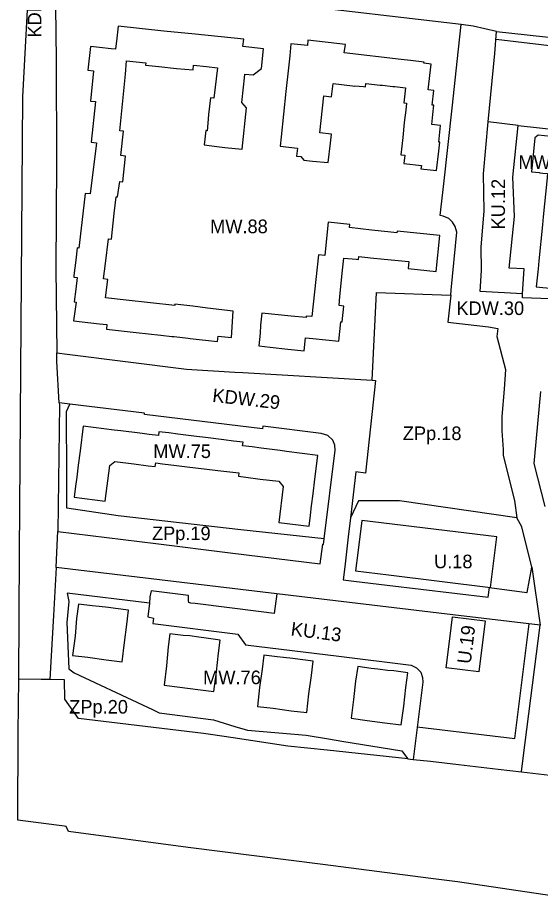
# Model space of a CAD drawing. Extents: x 7424434 to 7425898, y 5541432 to 5542659.
# Drawn here: x 7424612.8 to 7424804.8, y 5541529.8 to 5541854.6 of the extents above; entities that cross this region are included whole.
import ezdxf

# ---------------------------------------------------------------- set-up
doc = ezdxf.new("R2010")
doc.units = 0
for name, color, linetype in [('linie rozgraniczające', 7, 'Continuous'), ('nieprzekraczalne linie zabudowy', 7, 'Continuous'), ('obowiazujace linie zabudowy', 7, 'Continuous'), ('przeznaczenia terenów', 7, 'Continuous')]:
    doc.layers.add(name, color=color, linetype=linetype)

msp = doc.modelspace()

# ---------------------------------------------------------------- linework, layer by layer
at = {"layer": 'linie rozgraniczające'}
for p, q in [((7424614.73, 5541825.47), (7424617.47, 5541879.28)), ((7424626.71, 5541858.72), (7424626.92, 5541838.97)), ((7424775.7, 5541852), (7424710.49, 5541859.62)), ((7424774.72, 5541843.02), (7424775.7, 5541852)), ((7424780.17, 5541851.48), (7424775.7, 5541852)), ((7424788.7, 5541849.47), (7424780.17, 5541851.48)), ((7424788.02, 5541841.39), (7424788.7, 5541849.47)), ((7424788.7, 5541849.47), (7424827.16, 5541845.27)), ((7424772.35, 5541821.35), (7424774.72, 5541843.02)), ((7424785.67, 5541816.27), (7424788.02, 5541841.39)), ((7424626.92, 5541838.97), (7424627, 5541801.52)), ((7424613.5, 5541657.81), (7424614.73, 5541825.47)), ((7424769.3, 5541793.46), (7424772.35, 5541821.35)), ((7424783.89, 5541797.23), (7424785.67, 5541816.27)), ((7424796.69, 5541814.95), (7424785.67, 5541816.27)), ((7424794.7, 5541795.91), (7424796.69, 5541814.95)), ((7424796.69, 5541814.95), (7424823.5, 5541811.99)), ((7424627, 5541801.52), (7424626.85, 5541762.39)), ((7424784.16, 5541783.5), (7424783.89, 5541797.23)), ((7424795.25, 5541781.53), (7424794.7, 5541795.91)), ((7424768.03, 5541781.81), (7424769.3, 5541793.46)), ((7424783, 5541770.36), (7424784.16, 5541783.5)), ((7424769.11, 5541781.68), (7424768.03, 5541781.81)), ((7424771.15, 5541780.72), (7424769.11, 5541781.68)), ((7424772.47, 5541779.45), (7424771.15, 5541780.72)), ((7424773.53, 5541777.86), (7424772.47, 5541779.45)), ((7424793.29, 5541762.54), (7424795.25, 5541781.53)), ((7424774.13, 5541775.69), (7424773.53, 5541777.86)), ((7424772.08, 5541754.48), (7424774.13, 5541775.69)), ((7424783.12, 5541761.62), (7424783, 5541770.36)), ((7424626.85, 5541762.39), (7424627.15, 5541731.4)), ((7424782.68, 5541753.97), (7424783.12, 5541761.62)), ((7424798.83, 5541762.22), (7424793.29, 5541762.54)), ((7424798.3, 5541753.07), (7424798.83, 5541762.22)), ((7424742.99, 5541721.35), (7424744.63, 5541753.59)), ((7424744.63, 5541753.59), (7424771.9, 5541752.56)), ((7424771.9, 5541752.56), (7424772.08, 5541754.48)), ((7424798.3, 5541753.07), (7424782.68, 5541753.97)), ((7424771.9, 5541752.56), (7424770.83, 5541742.67)), ((7424798.21, 5541751.57), (7424798.3, 5541753.07)), ((7424808.23, 5541751.19), (7424798.21, 5541751.57)), ((7424770.83, 5541742.67), (7424785.72, 5541740.94)), ((7424785.72, 5541740.94), (7424789.13, 5541740.32)), ((7424789.13, 5541740.32), (7424788.86, 5541737.35)), ((7424788.86, 5541737.35), (7424792.02, 5541725.28)), ((7424627.15, 5541731.4), (7424631.02, 5541730.92)), ((7424627.18, 5541728.22), (7424627.15, 5541731.4)), ((7424631.02, 5541730.92), (7424674.77, 5541725.4)), ((7424628.06, 5541713.02), (7424627.18, 5541728.22)), ((7424674.77, 5541725.4), (7424692.52, 5541724.35)), ((7424692.52, 5541724.35), (7424695.52, 5541724.17)), ((7424695.52, 5541724.17), (7424740.9, 5541721.48)), ((7424792.02, 5541725.28), (7424791.47, 5541718.1)), ((7424744.22, 5541721.27), (7424740.61, 5541687.19)), ((7424740.9, 5541721.48), (7424740.93, 5541721.48)), ((7424740.93, 5541721.48), (7424742.99, 5541721.35)), ((7424742.99, 5541721.35), (7424744.22, 5541721.27)), ((7424791.47, 5541718.1), (7424790.65, 5541707.98)), ((7424804.86, 5541717.21), (7424802.63, 5541693.48)), ((7424628.1, 5541712.33), (7424627.5, 5541665.79)), ((7424631.9, 5541712.56), (7424628.06, 5541713.02)), ((7424628.06, 5541713.02), (7424628.1, 5541712.33)), ((7424630.69, 5541709.84), (7424631.9, 5541712.56)), ((7424659.37, 5541709.26), (7424631.9, 5541712.56)), ((7424630.82, 5541685.82), (7424630.69, 5541709.84)), ((7424659.32, 5541708.73), (7424659.37, 5541709.26)), ((7424702.71, 5541703.45), (7424659.32, 5541708.73)), ((7424790.65, 5541707.98), (7424790.62, 5541702.7)), ((7424702.84, 5541704.45), (7424702.71, 5541703.45)), ((7424724.33, 5541701.78), (7424702.84, 5541704.45)), ((7424726.78, 5541701.06), (7424724.33, 5541701.78)), ((7424790.62, 5541702.7), (7424791.08, 5541695.94)), ((7424728.52, 5541699.35), (7424726.78, 5541701.06)), ((7424729.35, 5541697.52), (7424728.52, 5541699.35)), ((7424725.33, 5541663), (7424729.36, 5541695.67)), ((7424729.36, 5541695.67), (7424729.35, 5541697.52)), ((7424791.08, 5541695.94), (7424791.18, 5541693.7)), ((7424791.18, 5541693.7), (7424795.32, 5541677.09)), ((7424802.63, 5541693.48), (7424802.41, 5541690.77)), ((7424802.41, 5541690.77), (7424806.44, 5541674.91)), ((7424630.89, 5541674.29), (7424630.82, 5541685.82)), ((7424736.97, 5541687.64), (7424735.02, 5541670.8)), ((7424740.61, 5541687.19), (7424736.97, 5541687.64)), ((7424737.97, 5541677.06), (7424735.02, 5541670.8)), ((7424753.11, 5541676.98), (7424737.97, 5541677.06)), ((7424796.14, 5541670.72), (7424753.11, 5541676.98)), ((7424795.32, 5541677.09), (7424796.14, 5541670.72)), ((7424649.75, 5541671.49), (7424630.89, 5541674.29)), ((7424694.71, 5541666.4), (7424649.75, 5541671.49)), ((7424735.02, 5541670.8), (7424734.21, 5541663.81)), ((7424798, 5541667.52), (7424796.14, 5541670.72)), ((7424627.47, 5541663.47), (7424627.5, 5541665.79)), ((7424627.5, 5541665.79), (7424663.55, 5541661.36)), ((7424725.33, 5541663), (7424694.71, 5541666.4)), ((7424801.7, 5541652.63), (7424798, 5541667.52)), ((7424626.87, 5541652.56), (7424627.47, 5541663.47)), ((7424725.09, 5541661.01), (7424725.33, 5541663)), ((7424734.21, 5541663.81), (7424732.93, 5541652.76)), ((7424663.55, 5541661.36), (7424690.81, 5541657.92)), ((7424723.94, 5541653.86), (7424724.84, 5541661.07)), ((7424724.84, 5541661.07), (7424725.09, 5541661.01)), ((7424613.16, 5541611.54), (7424613.5, 5541657.81)), ((7424690.81, 5541657.92), (7424723.94, 5541653.86)), ((7424732.93, 5541652.76), (7424732.38, 5541647.99)), ((7424626.87, 5541652.56), (7424626.38, 5541643.65)), ((7424708.02, 5541642.85), (7424626.87, 5541652.56)), ((7424799.99, 5541643.37), (7424801.7, 5541652.63)), ((7424801.7, 5541652.63), (7424804.72, 5541631.32)), ((7424732.38, 5541647.99), (7424736.33, 5541647.52)), ((7424736.33, 5541647.52), (7424748.53, 5541646.06)), ((7424626.38, 5541643.65), (7424625.89, 5541634.9)), ((7424661.18, 5541639.46), (7424631.01, 5541643.09)), ((7424631.01, 5541643.09), (7424631.59, 5541640.06)), ((7424661.85, 5541643.92), (7424661.28, 5541641.7)), ((7424663.83, 5541643.68), (7424661.85, 5541643.92)), ((7424675.53, 5541642.27), (7424663.83, 5541643.68)), ((7424748.53, 5541646.06), (7424785.68, 5541641.62)), ((7424785.68, 5541641.62), (7424786.11, 5541645.23)), ((7424786.11, 5541645.23), (7424799.81, 5541643.39)), ((7424799.81, 5541643.39), (7424799.99, 5541643.37)), ((7424631.59, 5541640.06), (7424630.86, 5541632.33)), ((7424661.28, 5541641.7), (7424661.18, 5541639.46)), ((7424675.52, 5541640.21), (7424675.53, 5541642.27)), ((7424675.67, 5541639.71), (7424675.52, 5541640.21)), ((7424676.45, 5541639.47), (7424675.67, 5541639.71)), ((7424708.02, 5541642.85), (7424706.99, 5541635.67)), ((7424772.65, 5541635.12), (7424708.02, 5541642.85)), ((7424661.18, 5541639.46), (7424660.55, 5541634.38)), ((7424677.96, 5541639.28), (7424676.45, 5541639.47)), ((7424702.23, 5541636.26), (7424677.96, 5541639.28)), ((7424625.89, 5541634.9), (7424625.07, 5541620.11)), ((7424660.55, 5541634.38), (7424662.73, 5541633.96)), ((7424662.73, 5541633.96), (7424662.46, 5541631.89)), ((7424706.99, 5541635.67), (7424702.23, 5541636.26)), ((7424771.52, 5541626.36), (7424772.55, 5541634.33)), ((7424772.55, 5541634.33), (7424784.56, 5541632.91)), ((7424804.72, 5541631.32), (7424772.65, 5541635.12)), ((7424630.86, 5541632.33), (7424631.58, 5541615.32)), ((7424662.46, 5541631.89), (7424693.7, 5541628.02)), ((7424784.56, 5541632.91), (7424782.16, 5541614.22)), ((7424798.54, 5541582.44), (7424804.72, 5541631.32)), ((7424693.7, 5541628.02), (7424696.44, 5541624.06)), ((7424696.44, 5541624.06), (7424730.76, 5541619.89)), ((7424770.15, 5541615.7), (7424771.52, 5541626.36)), ((7424625.07, 5541620.11), (7424624.59, 5541611.38)), ((7424730.76, 5541619.89), (7424757.33, 5541616.62)), ((7424631.58, 5541615.32), (7424633.57, 5541613.85)), ((7424633.57, 5541613.85), (7424658.59, 5541602.06)), ((7424757.33, 5541616.62), (7424759.36, 5541615.62)), ((7424759.36, 5541615.62), (7424760.91, 5541614.01)), ((7424760.91, 5541614.01), (7424761.55, 5541612.07)), ((7424782.16, 5541614.22), (7424770.15, 5541615.7)), ((7424613.02, 5541591.89), (7424613.16, 5541611.54)), ((7424621.47, 5541611.42), (7424613.16, 5541611.54)), ((7424624.59, 5541611.38), (7424621.47, 5541611.42)), ((7424630.02, 5541611.3), (7424624.59, 5541611.38)), ((7424630.12, 5541604.1), (7424630.02, 5541611.3)), ((7424761.55, 5541612.07), (7424761.62, 5541610.35)), ((7424761.62, 5541610.35), (7424758.13, 5541582)), ((7424635.1, 5541597.09), (7424630.12, 5541604.1)), ((7424658.59, 5541602.06), (7424662.37, 5541600.28)), ((7424662.37, 5541600.28), (7424664.02, 5541599.5)), ((7424664.02, 5541599.5), (7424664.78, 5541599.15)), ((7424664.78, 5541599.15), (7424684.73, 5541596.54)), ((7424681.05, 5541591.48), (7424635.1, 5541597.09)), ((7424684.73, 5541596.54), (7424692.54, 5541594.14)), ((7424612.78, 5541559.69), (7424613.02, 5541591.89)), ((7424683.68, 5541591.16), (7424681.05, 5541591.48)), ((7424691.99, 5541589.91), (7424683.68, 5541591.16)), ((7424692.54, 5541594.14), (7424697.23, 5541592.7)), ((7424697.23, 5541592.7), (7424718.77, 5541590.91)), ((7424711.98, 5541586.9), (7424691.99, 5541589.91)), ((7424718.77, 5541590.91), (7424726.95, 5541589.53)), ((7424726.95, 5541589.53), (7424731.93, 5541588.69)), ((7424731.93, 5541588.69), (7424753.86, 5541585.15)), ((7424726.43, 5541585.37), (7424711.98, 5541586.9)), ((7424756.07, 5541582.22), (7424726.43, 5541585.37)), ((7424753.86, 5541585.15), (7424755.98, 5541582.34)), ((7424755.98, 5541582.34), (7424756.07, 5541582.22)), ((7424756.07, 5541582.22), (7424758.13, 5541582)), ((7424758.13, 5541582), (7424764.44, 5541581.33)), ((7424764.44, 5541581.33), (7424774.67, 5541580.14)), ((7424797.91, 5541577.42), (7424798.54, 5541582.44)), ((7424774.67, 5541580.14), (7424789.28, 5541578.43)), ((7424789.28, 5541578.43), (7424797.91, 5541577.42)), ((7424797.91, 5541577.42), (7424808.28, 5541576.21)), ((7424627, 5541557.83), (7424612.78, 5541559.69)), ((7424629.98, 5541557.47), (7424627, 5541557.83)), ((7424630.65, 5541557.39), (7424629.98, 5541557.47)), ((7424631.49, 5541555.51), (7424630.65, 5541557.39)), ((7424675.46, 5541549.59), (7424631.49, 5541555.51)), ((7424724.85, 5541543.39), (7424675.46, 5541549.59)), ((7424764.52, 5541538.27), (7424724.85, 5541543.39)), ((7424774.35, 5541537), (7424764.52, 5541538.27)), ((7424822.67, 5541529.85), (7424774.35, 5541537))]:
    msp.add_line(p, q, dxfattribs=at)
at = {"layer": 'nieprzekraczalne linie zabudowy'}
msp.add_line((7424826.72, 5541842.04), (7424788.53, 5541846.49), dxfattribs=at)
for points in [[(7424788.86, 5541663.81), (7424739.16, 5541669.77), (7424737.73, 5541657.87), (7424736.84, 5541651.32), (7424748.99, 5541649.81), (7424786.45, 5541645.2), (7424788.86, 5541663.81)], [(7424759.52, 5541593.92), (7424795.43, 5541589.73), (7424800.75, 5541631.82)]]:
    msp.add_lwpolyline(points, dxfattribs=at)
at = {"layer": 'obowiazujace linie zabudowy'}
for points in [[(7424645.89, 5541758.41), (7424644.36, 5541758.59), (7424645.1, 5541764.22), (7424646.17, 5541773.27), (7424647.28, 5541773.14), (7424648.28, 5541782.62), (7424648.93, 5541788.75), (7424649.51, 5541788.69), (7424650.29, 5541794.38), (7424651.43, 5541794.27), (7424652.35, 5541803.72), (7424651.58, 5541803.8), (7424650.73, 5541803.88), (7424651.61, 5541812.85), (7424650.36, 5541812.97), (7424650.96, 5541819.05), (7424652.34, 5541833.77), (7424652.82, 5541838.73), (7424659.88, 5541837.93), (7424659.8, 5541837.15), (7424664.58, 5541836.61), (7424671.08, 5541835.87), (7424677.24, 5541835.42), (7424677.43, 5541837.13), (7424682.14, 5541836.6), (7424686.16, 5541836.15), (7424684.9, 5541825.01), (7424683.64, 5541825.15), (7424682.94, 5541819.01), (7424682.66, 5541815.75), (7424682.35, 5541813.02), (7424681.92, 5541813.07), (7424681.32, 5541807.79), (7424685.92, 5541807.27), (7424688.85, 5541806.86), (7424695.23, 5541806.25), (7424696.84, 5541821.37), (7424695.17, 5541823.39), (7424695.8, 5541829.06), (7424696.09, 5541832.45), (7424696.25, 5541833.85), (7424699.33, 5541833.51), (7424702.37, 5541835.83), (7424703.08, 5541843.14), (7424695.54, 5541843.96), (7424695.82, 5541846.62), (7424677.93, 5541848.51), (7424666.46, 5541849.65), (7424649.66, 5541851.42), (7424649.2, 5541847.08), (7424648.76, 5541842.95), (7424647.11, 5541843.13), (7424642.86, 5541843.58), (7424639.51, 5541843.93), (7424638.6, 5541835.27), (7424640.69, 5541835.05), (7424639.52, 5541823.94), (7424641.32, 5541823.75), (7424639.84, 5541808.81), (7424641.74, 5541808.62), (7424639.43, 5541789.81), (7424637.59, 5541790.01), (7424636.37, 5541779.24), (7424635.31, 5541769.88), (7424634.6, 5541769.96), (7424634.12, 5541765.51), (7424634.12, 5541765.51), (7424634.12, 5541765.51), (7424633.46, 5541759.86), (7424633.46, 5541759.86), (7424633.38, 5541759.25), (7424634.69, 5541759.08), (7424634.15, 5541754.77), (7424633.57, 5541750.12), (7424634.21, 5541750.04), (7424633.34, 5541743.11), (7424642.86, 5541742.08), (7424645.55, 5541741.79), (7424645.36, 5541740.13), (7424656.32, 5541738.87), (7424665.35, 5541737.89), (7424669.47, 5541737.45), (7424670.22, 5541737.35), (7424675.4, 5541736.79), (7424676.21, 5541736.69), (7424686.24, 5541735.61), (7424686.45, 5541737.56), (7424691.28, 5541737.04), (7424691.95, 5541746.73), (7424682.5, 5541747.77), (7424677.07, 5541748.53), (7424670.56, 5541749.25), (7424670.51, 5541748.78), (7424652.59, 5541750.74), (7424645.1, 5541751.56)], [(7424726.91, 5541801.33), (7424727.72, 5541808.45), (7424728.1, 5541811.8), (7424723.76, 5541812.29), (7424725.3, 5541825.82), (7424728.12, 5541825.5), (7424728.67, 5541830.33), (7424735.84, 5541829.52), (7424736.61, 5541829.43), (7424736.63, 5541829.57), (7424739.82, 5541829.21), (7424740.58, 5541829.12), (7424740.73, 5541830.41), (7424745.99, 5541829.81), (7424746.83, 5541829.7), (7424750.63, 5541829.27), (7424751.4, 5541829.25), (7424755.3, 5541828.81), (7424754.68, 5541823.3), (7424755.64, 5541823.19), (7424755.35, 5541820.63), (7424754.83, 5541816.02), (7424754.3, 5541810.52), (7424753.58, 5541804.16), (7424755.05, 5541803.99), (7424754.7, 5541800.96), (7424761.09, 5541800.23), (7424760.95, 5541799), (7424766.66, 5541798.35), (7424767.48, 5541805.55), (7424767.85, 5541808.81), (7424767.46, 5541808.85), (7424768.15, 5541814.92), (7424764.92, 5541815.29), (7424765.34, 5541819.02), (7424765.72, 5541822.38), (7424765.1, 5541822.45), (7424765.7, 5541827.75), (7424763.57, 5541827.99), (7424764.66, 5541837.53), (7424762.04, 5541837.83), (7424762.09, 5541838.24), (7424757.11, 5541838.8), (7424753.67, 5541839.21), (7424732.77, 5541841.58), (7424733.17, 5541844.69), (7424719.42, 5541846.25), (7424719.24, 5541844.39), (7424713.19, 5541844.99), (7424712.72, 5541840.57), (7424712.25, 5541836.18), (7424711.32, 5541827.44), (7424709.63, 5541810.76), (7424709.22, 5541807.29), (7424715.6, 5541806.6), (7424715.22, 5541803.72), (7424716.8, 5541803.52), (7424717.89, 5541802.18), (7424721.13, 5541801.88)], [(7424815.73, 5541754.48), (7424820.7, 5541803.05), (7424821.28, 5541808.59), (7424820.3, 5541809.73), (7424803.98, 5541811.34), (7424802.79, 5541810.42), (7424801.55, 5541797.91), (7424804.53, 5541797.63), (7424804.52, 5541797.49), (7424805.76, 5541797.39), (7424807.46, 5541797.25), (7424807.17, 5541794.47), (7424805.86, 5541781.32), (7424805.58, 5541778.41), (7424804.23, 5541765.22), (7424803.94, 5541762.25), (7424803.29, 5541755.69)], [(7424701.38, 5541733.96), (7424705.52, 5541733.46), (7424712.03, 5541732.76), (7424718.07, 5541732.15), (7424718.56, 5541736.94), (7424721.23, 5541736.67), (7424730.79, 5541735.71), (7424731.5, 5541742.79), (7424732.05, 5541742.74), (7424732.64, 5541748.59), (7424730.84, 5541748.77), (7424731.18, 5541752.11), (7424732.16, 5541761.78), (7424732.61, 5541766.21), (7424737.12, 5541765.76), (7424738.03, 5541765.67), (7424738.15, 5541766.8), (7424741.44, 5541766.47), (7424742.38, 5541766.36), (7424747.45, 5541765.85), (7424756.48, 5541764.93), (7424756.22, 5541762.33), (7424766.53, 5541761.29), (7424767.86, 5541774.51), (7424752.14, 5541776.1), (7424752.09, 5541775.53), (7424748.74, 5541775.89), (7424742.76, 5541776.53), (7424734.67, 5541777.4), (7424734.79, 5541778.52), (7424726.9, 5541779.37), (7424725.87, 5541769.8), (7424725.87, 5541769.8), (7424725.59, 5541767.19), (7424723.25, 5541767.44), (7424720.8, 5541744.75), (7424718.82, 5541744.92), (7424718.77, 5541744.37), (7424713.26, 5541744.93), (7424702.43, 5541746.03), (7424701.97, 5541741.51), (7424701.85, 5541738.6)], [(7424644.92, 5541676.95), (7424646.61, 5541689.98), (7424648.42, 5541691.43), (7424655.51, 5541690.58), (7424660.67, 5541689.91), (7424663.33, 5541689.6), (7424663.49, 5541690.94), (7424665.94, 5541690.65), (7424671.18, 5541689.97), (7424676.01, 5541689.4), (7424681.27, 5541688.78), (7424686.31, 5541688.18), (7424694.05, 5541687.26), (7424693.91, 5541686.06), (7424696.57, 5541685.74), (7424701.83, 5541685.02), (7424708.67, 5541684.2), (7424710.37, 5541682.23), (7424708.75, 5541669.01), (7424719.81, 5541667.66), (7424720.32, 5541671.77), (7424720.77, 5541675.22), (7424721.3, 5541679.57), (7424722.01, 5541684.98), (7424723.06, 5541693.72), (7424711.59, 5541695.11), (7424709.23, 5541695.51), (7424702.21, 5541696.36), (7424698.91, 5541696.82), (7424695.41, 5541697.25), (7424695.57, 5541698.58), (7424692.13, 5541699), (7424688.54, 5541699.46), (7424681.84, 5541700.28), (7424678.47, 5541700.65), (7424671.68, 5541701.49), (7424668.32, 5541701.97), (7424664.63, 5541702.43), (7424664.46, 5541701.02), (7424661.03, 5541701.44), (7424657.72, 5541701.85), (7424650.7, 5541702.71), (7424648.24, 5541703.02), (7424636.9, 5541704.41), (7424635.8, 5541695.44), (7424635.03, 5541690.09), (7424634.49, 5541685.66), (7424634.06, 5541682.45), (7424633.55, 5541678.35)], [(7424632.94, 5541620.24), (7424638.58, 5541619.51), (7424645.31, 5541618.65), (7424651.15, 5541617.91), (7424652.07, 5541625.01), (7424652.86, 5541631.61), (7424653.53, 5541636.83), (7424648.66, 5541637.46), (7424646.1, 5541637.76), (7424642.78, 5541638.19), (7424640.1, 5541638.45), (7424635.12, 5541639.1), (7424634.44, 5541633.83), (7424633.86, 5541627.27)], [(7424666.54, 5541609.24), (7424672.35, 5541608.49), (7424679, 5541607.67), (7424684.86, 5541606.91), (7424685.8, 5541614.14), (7424686.54, 5541621.05), (7424687.17, 5541625.87), (7424682, 5541626.54), (7424679.39, 5541626.91), (7424676.03, 5541627.35), (7424673.56, 5541627.53), (7424668.72, 5541628.16), (7424668.09, 5541623.32), (7424667.49, 5541616.44)], [(7424703.18, 5541620.27), (7424702.63, 5541615.18), (7424701.62, 5541608.47), (7424700.87, 5541601.49), (7424706.66, 5541600.87), (7424713.25, 5541599.86), (7424718.99, 5541599.24), (7424719.73, 5541606.15), (7424720.73, 5541612.89), (7424721.3, 5541618.16), (7424716.52, 5541618.67), (7424713.89, 5541619.03), (7424710.46, 5541619.4), (7424708.12, 5541619.73)], [(7424735.24, 5541597.1), (7424741.15, 5541596.27), (7424747.64, 5541595.49), (7424753.61, 5541594.65), (7424754.59, 5541601.6), (7424755.41, 5541608.41), (7424756.17, 5541613.79), (7424751.01, 5541614.51), (7424748.63, 5541614.67), (7424745.04, 5541615.18), (7424742.68, 5541615.42), (7424737.7, 5541616.12), (7424736.95, 5541610.81), (7424736.21, 5541604)]]:
    msp.add_lwpolyline(points, close=True, dxfattribs=at)

# ---------------------------------------------------------------- texts
at = {"layer": 'przeznaczenia terenów'}
for s, rotation, p in [('KDL.1', 90, (7424621.48, 5541847.26)), ('KU.12', 90, (7424791.81, 5541776.75)), ('KDW.29', 353.6257, (7424684.13, 5541713.39)), ('KU.13', 352.782, (7424712.92, 5541627.58)), ('U.19', 83.0629, (7424779.2, 5541616.92))]:
    msp.add_text(s, height=5, rotation=rotation, dxfattribs=at).set_placement(p)
for s, p in [('MW.89', (7424796.73, 5541798.98)), ('MW.88', (7424683.49, 5541775.37)), ('KDW.30', (7424773.95, 5541745.3)), ('ZPp.18', (7424754.27, 5541699.34)), ('MW.75', (7424662.61, 5541692.74)), ('ZPp.19', (7424662.12, 5541662.58)), ('U.18', (7424765.75, 5541652.23)), ('MW.76', (7424680.92, 5541609.64)), ('ZPp.20', (7424631.73, 5541598.83))]:
    msp.add_text(s, height=5, dxfattribs=at).set_placement(p)

doc.saveas('drawing.dxf')
